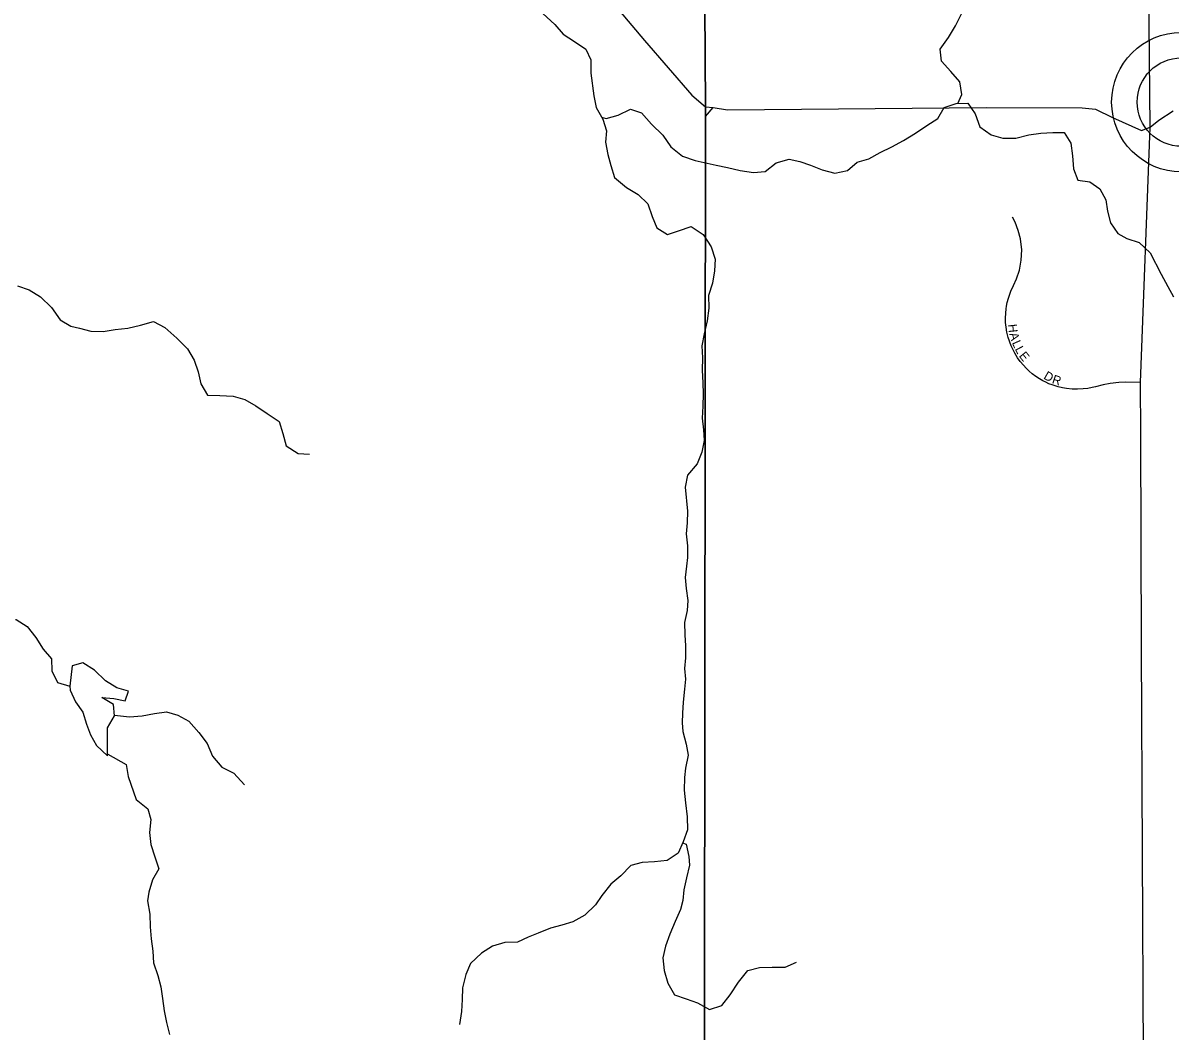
# Model space of a CAD drawing. Extents: x 1985906 to 2277390, y 930619 to 1324581.
# Drawn here: x 2161796 to 2168256, y 1124636 to 1130314 of the extents above; entities that cross this region are included whole.
import ezdxf

# ---------------------------------------------------------------- set-up
doc = ezdxf.new("R2010")
doc.units = 0
for name, color, linetype in [('GM_X_County_Road', 7, 'Continuous'), ('GM_X_Minor_Lake', 7, 'Continuous'), ('GM_X_Minor_River', 7, 'Continuous'), ('GM_X_State_Route', 7, 'Continuous'), ('GM_X_Township', 7, 'Continuous'), ('GM_X_Township_Road', 7, 'Continuous'), ('GM_X_Township_Subdivision', 7, 'Continuous'), ('GM_X_Township_Subdivision_Text', 7, 'Continuous'), ('GM_X_Unincorporated', 7, 'Continuous')]:
    doc.layers.add(name, color=color, linetype=linetype)

msp = doc.modelspace()

# ---------------------------------------------------------------- linework, layer by layer
at = {"layer": 'GM_X_County_Road'}
msp.add_lwpolyline([(2165632.9, 1123203.2), (2165639.1, 1129787.2), (2165683.2, 1129836.7)], dxfattribs=at)
at = {"layer": 'GM_X_Minor_Lake'}
for points in [[(2162272.6, 1126252.1), (2162272.3, 1126344.2), (2162312, 1126410.4), (2162305.7, 1126474.4), (2162239.6, 1126514.2), (2162307.6, 1126508.5), (2162371.6, 1126494.7), (2162391.4, 1126550.9), (2162325.3, 1126568.6), (2162261.2, 1126608.4), (2162199, 1126668.2), (2162132.8, 1126709.9), (2162072.9, 1126693.6), (2162059.3, 1126577.4)], [(2162059.3, 1126577.4), (2162061.5, 1126555.4), (2162091.7, 1126489.5), (2162134, 1126431.6), (2162154.2, 1126363.7), (2162176.5, 1126303.7), (2162210.7, 1126243.8), (2162272.9, 1126186), (2162272.6, 1126252.1)], [(2162059.4, 1126577.5), (2162061.5, 1126555.4), (2162091.7, 1126489.5), (2162134, 1126431.6), (2162154.2, 1126363.7), (2162176.5, 1126303.7), (2162210.7, 1126243.8), (2162272.9, 1126186), (2162272.6, 1126252.1)]]:
    msp.add_lwpolyline(points, dxfattribs=at)
at = {"layer": 'GM_X_Minor_River'}
for points in [[(2164724.7, 1130366.8), (2164791, 1130305), (2164839.2, 1130251.2), (2164901.3, 1130209.4), (2164965.5, 1130165.6), (2164993.7, 1130105.7), (2164994, 1130031.6), (2165010.5, 1129903.6), (2165024.8, 1129837.6), (2165061, 1129771.6), (2165083.3, 1129705.7), (2165077.6, 1129641.6), (2165089.8, 1129573.6), (2165106.1, 1129511.6), (2165128.4, 1129443.6), (2165194.6, 1129387.8), (2165260.7, 1129348.1), (2165314.9, 1129294.3), (2165339.2, 1129224.3), (2165365.4, 1129160.3), (2165425.6, 1129122.6), (2165487.4, 1129142.8), (2165559.3, 1129167.2), (2165627.5, 1129121.4), (2165671.7, 1129053.6), (2165694, 1128983.6), (2165690.3, 1128917.5), (2165678.6, 1128847.4), (2165656.9, 1128779.2), (2165659.2, 1128707.1), (2165649.5, 1128635), (2165631.8, 1128562.9), (2165620, 1128494.8), (2165622.3, 1128426.7), (2165620.6, 1128358.6), (2165624.9, 1128286.6), (2165627.1, 1128224.5), (2165625.4, 1128154.4), (2165621.7, 1128088.4), (2165628, 1128022.3), (2165632.2, 1127962.3), (2165618.5, 1127896.1), (2165592.8, 1127830), (2165539.1, 1127765.7), (2165525.3, 1127699.6), (2165537.9, 1127563.5), (2165536.2, 1127497.4), (2165530.4, 1127435.3), (2165538.7, 1127369.3), (2165539, 1127303.2), (2165533.2, 1127253.1), (2165525.4, 1127191), (2165531.7, 1127129), (2165540, 1127061), (2165536.2, 1127004.9), (2165522.5, 1126936.8), (2165522.8, 1126866.7), (2165527, 1126804.7), (2165527.3, 1126738.6), (2165521.5, 1126678.5), (2165527.8, 1126618.5), (2165522, 1126560.4), (2165514.3, 1126488.3), (2165510.6, 1126426.2), (2165508.8, 1126372.2), (2165513, 1126322.1), (2165531.3, 1126252.1), (2165541.5, 1126190.1), (2165527.8, 1126116), (2165522, 1126063.9), (2165520.3, 1125991.8), (2165526.6, 1125921.8), (2165537, 1125841.8), (2165539.2, 1125769.7), (2165513.5, 1125701.5), (2165485.8, 1125637.3), (2165424, 1125597), (2165352.1, 1125588.7), (2165284.1, 1125584.4), (2165220.2, 1125568.1), (2165162.5, 1125509.8), (2165106.7, 1125463.5), (2165057, 1125399.2), (2165021.2, 1125347.1), (2164959.5, 1125288.7), (2164893.7, 1125250.4), (2164831.8, 1125232.1), (2164767.8, 1125215.8), (2164698, 1125187.5), (2164642.1, 1125165.2), (2164580.3, 1125136.9), (2164510.3, 1125134.6), (2164440.4, 1125114.3), (2164378.6, 1125074), (2164316.9, 1125015.7), (2164291.1, 1124953.5), (2164271.4, 1124879.4), (2164269.7, 1124813.3), (2164266, 1124745.2), (2164254.3, 1124673.1)], [(2167061.8, 1129860.6), (2167083.6, 1129910.5), (2167071.4, 1129982.5), (2167021.1, 1130040.4), (2166968.9, 1130098.2), (2166960.6, 1130166.2), (2167008.4, 1130232.5), (2167048.1, 1130296.7), (2167081.8, 1130364.9)], [(2165054.5, 1129783.6), (2165081, 1129775.7), (2165148.9, 1129794.1), (2165216.7, 1129828.4), (2165278.8, 1129806.6), (2165335.1, 1129742.8), (2165399.3, 1129681), (2165445.5, 1129615.1), (2165509.7, 1129563.4), (2165581.8, 1129539.7), (2165649.8, 1129523.9), (2165699.8, 1129512.1), (2165763.9, 1129500.4), (2165835.9, 1129482.7), (2165909.9, 1129471), (2165975.9, 1129477.3), (2166037.6, 1129525.6), (2166111.5, 1129545.9), (2166171.6, 1129534.2), (2166231.6, 1129512.4), (2166297.7, 1129486.7), (2166367.8, 1129467), (2166439.7, 1129483.3), (2166493.4, 1129529.6), (2166559.3, 1129547.9), (2166623.2, 1129584.2), (2166689, 1129616.5), (2166754.8, 1129650.8), (2166822.6, 1129693.1), (2166886.4, 1129735.5), (2166948.3, 1129775.8), (2166984, 1129838), (2167051.9, 1129860.3), (2167117.8, 1129862.6), (2167158.1, 1129802.7), (2167184.4, 1129728.7), (2167248.5, 1129683), (2167314.6, 1129665.2), (2167388.5, 1129665.6), (2167460.4, 1129683.9), (2167528.4, 1129692.2), (2167596.3, 1129696.5), (2167660.3, 1129696.8), (2167696.5, 1129636.8), (2167706.8, 1129564.8), (2167713.1, 1129492.8), (2167737.4, 1129428.8), (2167803.4, 1129419.1), (2167861.5, 1129379.3), (2167893.7, 1129317.4), (2167904, 1129253.3), (2167920.3, 1129187.3), (2167962.5, 1129127.5), (2168012.6, 1129099.7), (2168082.6, 1129077.9), (2168144.9, 1129018.1), (2168205.3, 1128898.3), (2168243.6, 1128828.4), (2168275.8, 1128770.4)], [(2167057.5, 1129860.5), (2167057.5, 1129860.4)], [(2161766.3, 1128832.4), (2161830.3, 1128810.7), (2161894.5, 1128770.9), (2161956.7, 1128711.2), (2162005, 1128641.3), (2162065.1, 1128605.5), (2162115.1, 1128593.7), (2162179.1, 1128578), (2162247.1, 1128576.3), (2162315, 1128586.6), (2162387, 1128594.9), (2162458.9, 1128611.2), (2162530.8, 1128631.6), (2162594.9, 1128597.8), (2162663.1, 1128538.1), (2162723.3, 1128478.2), (2162759.6, 1128414.3), (2162783.8, 1128348.4), (2162798.1, 1128280.4), (2162836.3, 1128216.5), (2162904.3, 1128214.8), (2162980.3, 1128211.1), (2163046.3, 1128193.4), (2163108.5, 1128157.6), (2163170.6, 1128113.8), (2163238.8, 1128068.1), (2163259, 1128002.1), (2163279.3, 1127932.1), (2163345.5, 1127888.3), (2163409.5, 1127884.6)], [(2161753.8, 1126954.3), (2161758, 1126954.5), (2161820.1, 1126914.8), (2161868.4, 1126852.9), (2161910.6, 1126787), (2161956.8, 1126731.2), (2161959.1, 1126665.1), (2161991.3, 1126599.2), (2162059.4, 1126577.5)], [(2162311.7, 1126414), (2162396, 1126404.8), (2162467.9, 1126411.1), (2162537.8, 1126423.4), (2162603.8, 1126433.7), (2162667.8, 1126413.9), (2162729.9, 1126380.2), (2162786.2, 1126316.4), (2162834.4, 1126254.5), (2162862.7, 1126184.6), (2162916.9, 1126122.7), (2162983, 1126089), (2163043.3, 1126023.2)], [(2162273.5, 1126194.2), (2162377.1, 1126136.4), (2162389.4, 1126068.4), (2162433.9, 1125940.5), (2162500.1, 1125886.7), (2162516.3, 1125826.7), (2162508.6, 1125754.6), (2162516.9, 1125686.6), (2162539.2, 1125616.6), (2162561.4, 1125548.6), (2162525.7, 1125486.4), (2162506, 1125418.3), (2162498.2, 1125368.2), (2162510.5, 1125294.2), (2162512.8, 1125222.1), (2162519.1, 1125154.1), (2162527.3, 1125086), (2162531.6, 1125020), (2162555.9, 1124948), (2162572.1, 1124884), (2162582.4, 1124818), (2162590.7, 1124750), (2162605, 1124684), (2162621.2, 1124616)], [(2165510.9, 1125695.5), (2165531.6, 1125687.6), (2165545.9, 1125619.6), (2165550.1, 1125569.5), (2165532.4, 1125499.4), (2165518.6, 1125431.3), (2165512.9, 1125371.2), (2165499.1, 1125321.1), (2165469.4, 1125252.9), (2165439.7, 1125180.7), (2165414, 1125114.5), (2165400.3, 1125048.4), (2165406.6, 1124976.3), (2165426.9, 1124904.4), (2165465.1, 1124840.5), (2165531.2, 1124816.7), (2165595.2, 1124795), (2165663.4, 1124757.2), (2165731.2, 1124779.6), (2165779, 1124839.8), (2165826.7, 1124910.1), (2165878.4, 1124976.4), (2165944.3, 1124992.7), (2166016.2, 1124995), (2166088.2, 1124995.3), (2166152.1, 1125023.6)]]:
    msp.add_lwpolyline(points, dxfattribs=at)
at = {"layer": 'GM_X_State_Route'}
msp.add_lwpolyline([(2165032.2, 1130529.9), (2165296.7, 1130214), (2165562.3, 1129906.3), (2165639.2, 1129840.4), (2165683.2, 1129836.7), (2165763.7, 1129823.9), (2167220.4, 1129837.8), (2167760.2, 1129836.5), (2167836.5, 1129828.9), (2167932.6, 1129781.6), (2168095.8, 1129708.3), (2168143.2, 1129726.6), (2168192.1, 1129766.3), (2168274.5, 1129818.2)], dxfattribs=at)
at = {"layer": 'GM_X_Township'}
for points in [[(2148868.6, 1143156.5), (2158191.1, 1143237.8), (2158223.8, 1143235.3), (2159339.8, 1143195.5), (2160317.4, 1143220.4), (2160904.6, 1143234.6), (2161258.7, 1143239.3), (2162172.1, 1143244.2), (2162565.3, 1143246.3), (2162948.2, 1143251.3), (2163253.9, 1143246.8), (2163409.6, 1143245.2), (2164236.3, 1143254.7), (2165482.4, 1143254), (2165573.1, 1143254.9), (2165564.4, 1142857.3), (2165573.1, 1140167.1), (2165566, 1137828.9), (2165588.2, 1136701.9), (2165594.2, 1136655.6), (2165639.2, 1129840.4), (2165639.1, 1129787.2), (2165632.9, 1123203.2)], [(2165632.9, 1123203.2), (2165639.1, 1129787.2), (2165639.2, 1129840.4), (2165594.2, 1136655.6), (2165588.2, 1136701.9), (2165566, 1137828.9), (2165573.1, 1140167.1), (2165564.4, 1142857.3), (2165573.1, 1143254.9), (2168137.3, 1143273.8), (2168310.4, 1143281.3)]]:
    msp.add_lwpolyline(points, dxfattribs=at)
at = {"layer": 'GM_X_Township_Road'}
for points in [[(2168091.1, 1127999.8), (2168089.9, 1128289.3), (2168143.2, 1129726.6), (2168106.2, 1133629.9), (2168108.2, 1133977.3), (2168103.3, 1134978.3), (2168150.8, 1136581.7)], [(2168138.9, 1123211.9), (2168105.8, 1124487.9), (2168096.2, 1126794.5), (2168091.1, 1127999.8)]]:
    msp.add_lwpolyline(points, dxfattribs=at)
at = {"layer": 'GM_X_Township_Subdivision'}
msp.add_lwpolyline([(2168089.9, 1128289.3), (2168006.9, 1128290.7), (2167966.9, 1128289.1), (2167919.3, 1128283.7), (2167879.4, 1128276.2), (2167836.9, 1128265), (2167817.7, 1128260.1), (2167793.5, 1128255.4), (2167766.9, 1128252), (2167735, 1128250.3), (2167704.6, 1128251.1), (2167673.5, 1128254.3), (2167649.6, 1128258.4), (2167626.9, 1128263.7), (2167609.2, 1128268.9), (2167592.7, 1128274.5), (2167574.1, 1128281.8), (2167555.8, 1128290.1), (2167539.2, 1128298.6), (2167521.1, 1128309), (2167501.1, 1128322), (2167480.1, 1128337.6), (2167462.1, 1128352.9), (2167445.2, 1128369.1), (2167429.9, 1128385.5), (2167412.5, 1128406.5), (2167397.2, 1128427.8), (2167381.3, 1128453.6), (2167361, 1128495.1), (2167344.3, 1128542.7), (2167337.4, 1128571.6), (2167332.8, 1128599.3), (2167330.2, 1128626.5), (2167329.5, 1128650.1), (2167330.5, 1128678.5), (2167333.2, 1128704.4), (2167335.4, 1128719), (2167339.3, 1128738.6), (2167345.9, 1128763.8), (2167359.8, 1128803.2), (2167375, 1128835.8), (2167392.1, 1128872.9), (2167408.1, 1128921.6), (2167418.5, 1128978.2), (2167420.6, 1129036.6), (2167413.8, 1129096.9), (2167401.3, 1129145.3), (2167383.3, 1129191.2), (2167368.4, 1129220)], dxfattribs=at)
at = {"layer": 'GM_X_Unincorporated'}
for radius in [392.8, 249]:
    msp.add_circle((2168320, 1129867.9), radius, dxfattribs=at)

# ---------------------------------------------------------------- texts
at = {"layer": 'GM_X_Township_Subdivision_Text'}
for s, rotation, p in [('H', 276.15433, (2167343.6, 1128615.3)), ('A', 285.47943, (2167350, 1128562.8)), ('L', 293.85348, (2167364.4, 1128512.9)), ('L', 298.07062, (2167380.4, 1128477.1)), ('E', 308.68395, (2167402.5, 1128437.6)), ('D', 330.13853, (2167540, 1128312.2)), ('R', 341.51373, (2167587.8, 1128286))]:
    msp.add_text(s, height=50, rotation=rotation, dxfattribs=at).set_placement(p)

doc.saveas('drawing.dxf')
